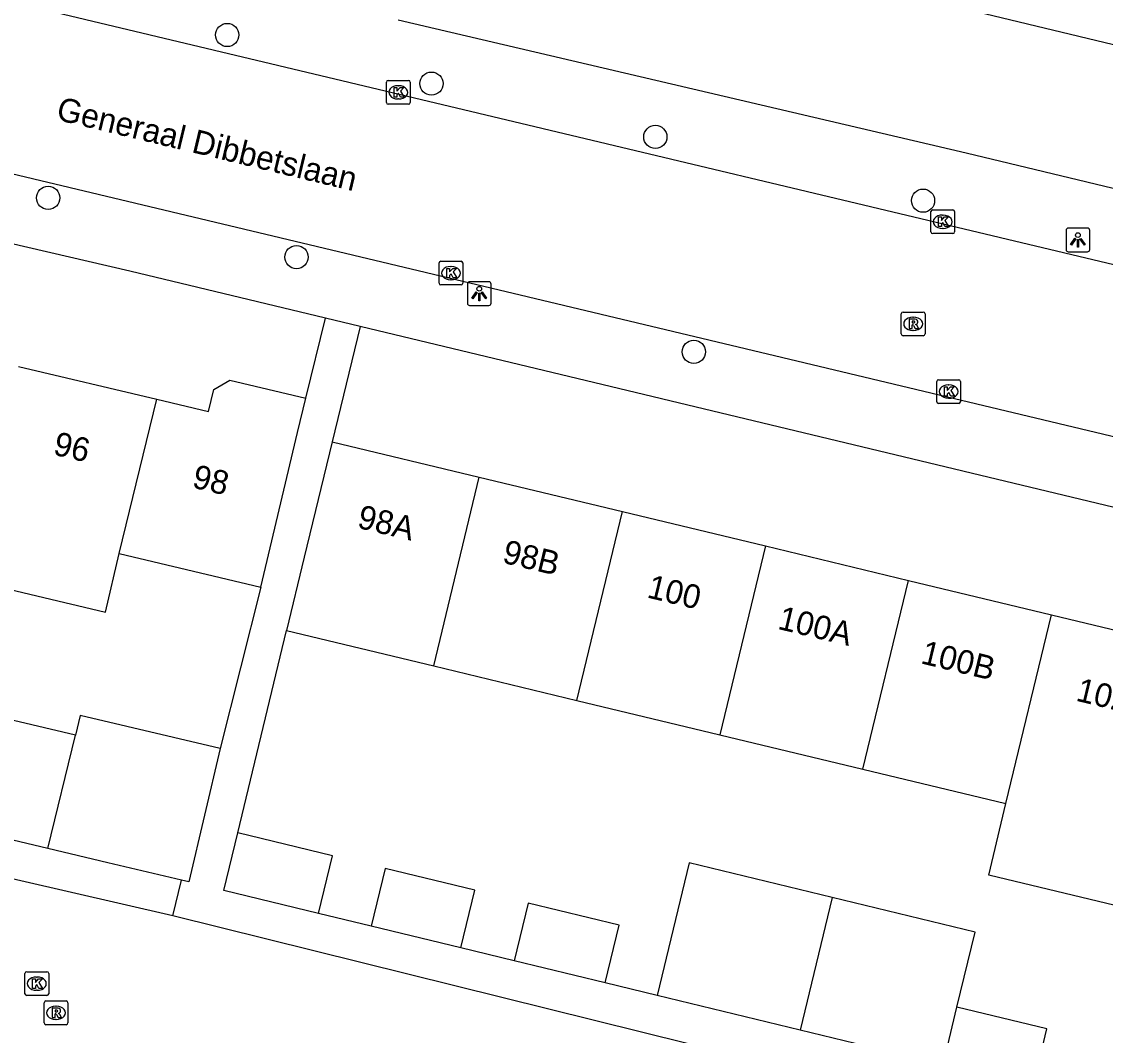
# Model space of a CAD drawing. Extents: x 161084 to 161928, y 385355 to 386522.
# Drawn here: x 161373.77 to 161419.44, y 385813.15 to 385855.89 of the extents above; entities that cross this region are included whole.
import ezdxf

# ---------------------------------------------------------------- set-up
doc = ezdxf.new("R2010")
doc.units = 0
for name, color, linetype in [('IMGEO_Boom', 7, 'Continuous'), ('IMGEO_Kolk', 7, 'Continuous'), ('IMGEO_Lichtpunt', 7, 'Continuous'), ('IMGEO_Openbare_ruimte_label', 7, 'Continuous'), ('IMGEO_Pand', 7, 'Continuous'), ('IMGEO_Pand_nummerreeks', 7, 'Continuous'), ('IMGEO_Rijbaan_lokaal_open', 7, 'Continuous'), ('IMGEO_Rioolput', 7, 'Continuous'), ('IMGEO_Voetpad_open', 7, 'Continuous')]:
    doc.layers.add(name, color=color, linetype=linetype)

msp = doc.modelspace()

# ---------------------------------------------------------------- linework, layer by layer
at = {"layer": 'IMGEO_Boom'}
for centre in [(161382.429, 385855.324), (161391.039, 385853.273), (161400.475, 385851.026), (161374.883, 385848.457), (161411.759, 385848.339), (161385.35, 385845.96), (161402.097, 385841.965)]:
    msp.add_circle(centre, 0.489, dxfattribs=at)
at = {"layer": 'IMGEO_Kolk'}
for p, q in [((161389.141, 385852.48), (161389.141, 385853.332)), ((161389.216, 385853.406), (161390.068, 385853.406)), ((161389.629, 385853.186), (161389.654, 385853.186)), ((161390.142, 385853.332), (161390.142, 385852.48)), ((161390.068, 385852.406), (161389.216, 385852.406)), ((161389.652, 385852.626), (161389.627, 385852.626)), ((161412.089, 385847.024), (161412.089, 385847.876)), ((161412.164, 385847.95), (161413.016, 385847.95)), ((161412.577, 385847.73), (161412.602, 385847.73)), ((161413.09, 385847.876), (161413.09, 385847.024)), ((161413.016, 385846.95), (161412.164, 385846.95)), ((161412.6, 385847.17), (161412.575, 385847.17)), ((161391.36, 385844.859), (161391.36, 385845.711)), ((161391.435, 385845.785), (161392.287, 385845.785)), ((161391.848, 385845.565), (161391.873, 385845.565)), ((161392.361, 385845.711), (161392.361, 385844.859)), ((161391.871, 385845.005), (161391.846, 385845.005)), ((161392.287, 385844.785), (161391.435, 385844.785)), ((161412.411, 385840.789), (161413.263, 385840.789)), ((161412.336, 385839.863), (161412.336, 385840.715)), ((161412.824, 385840.569), (161412.849, 385840.569)), ((161413.337, 385840.715), (161413.337, 385839.863)), ((161412.847, 385840.009), (161412.822, 385840.009)), ((161413.263, 385839.789), (161412.411, 385839.789)), ((161373.904, 385814.901), (161373.904, 385815.753)), ((161373.979, 385815.827), (161374.831, 385815.827)), ((161374.905, 385815.753), (161374.905, 385814.901)), ((161374.392, 385815.607), (161374.417, 385815.607)), ((161374.831, 385814.827), (161373.979, 385814.827)), ((161374.415, 385815.047), (161374.39, 385815.047))]:
    msp.add_line(p, q, dxfattribs=at)
for points in [[(161389.141, 385852.48), (161389.141, 385853.332)], [(161389.216, 385853.406), (161390.068, 385853.406)], [(161390.142, 385853.332), (161390.142, 385852.48)], [(161389.462, 385853.106), (161389.585, 385853.106), (161389.585, 385852.955), (161389.715, 385853.106), (161389.879, 385853.106), (161389.733, 385852.955), (161389.886, 385852.706), (161389.734, 385852.706), (161389.649, 385852.87), (161389.585, 385852.803), (161389.585, 385852.706), (161389.462, 385852.706), (161389.462, 385853.106)], [(161390.068, 385852.406), (161389.216, 385852.406)], [(161412.089, 385847.024), (161412.089, 385847.876)], [(161412.164, 385847.95), (161413.016, 385847.95)], [(161412.41, 385847.65), (161412.533, 385847.65), (161412.533, 385847.499), (161412.663, 385847.65), (161412.827, 385847.65), (161412.681, 385847.499), (161412.834, 385847.25), (161412.682, 385847.25), (161412.597, 385847.414), (161412.533, 385847.347), (161412.533, 385847.25), (161412.41, 385847.25), (161412.41, 385847.65)], [(161413.09, 385847.876), (161413.09, 385847.024)], [(161413.016, 385846.95), (161412.164, 385846.95)], [(161391.36, 385844.859), (161391.36, 385845.711)], [(161391.435, 385845.785), (161392.287, 385845.785)], [(161391.681, 385845.485), (161391.804, 385845.485), (161391.804, 385845.334), (161391.934, 385845.485), (161392.098, 385845.485), (161391.952, 385845.334), (161392.105, 385845.085), (161391.953, 385845.085), (161391.868, 385845.249), (161391.804, 385845.182), (161391.804, 385845.085), (161391.681, 385845.085), (161391.681, 385845.485)], [(161392.361, 385845.711), (161392.361, 385844.859)], [(161392.287, 385844.785), (161391.435, 385844.785)], [(161412.411, 385840.789), (161413.263, 385840.789)], [(161412.336, 385839.863), (161412.336, 385840.715)], [(161412.657, 385840.489), (161412.78, 385840.489), (161412.78, 385840.338), (161412.91, 385840.489), (161413.074, 385840.489), (161412.928, 385840.338), (161413.081, 385840.089), (161412.929, 385840.089), (161412.844, 385840.253), (161412.78, 385840.186), (161412.78, 385840.089), (161412.657, 385840.089), (161412.657, 385840.489)], [(161413.337, 385840.715), (161413.337, 385839.863)], [(161413.263, 385839.789), (161412.411, 385839.789)], [(161373.904, 385814.901), (161373.904, 385815.753)], [(161373.979, 385815.827), (161374.831, 385815.827)], [(161374.905, 385815.753), (161374.905, 385814.901)], [(161374.225, 385815.527), (161374.348, 385815.527), (161374.348, 385815.376), (161374.478, 385815.527), (161374.642, 385815.527), (161374.496, 385815.376), (161374.649, 385815.127), (161374.497, 385815.127), (161374.412, 385815.291), (161374.348, 385815.224), (161374.348, 385815.127), (161374.225, 385815.127), (161374.225, 385815.527)], [(161374.831, 385814.827), (161373.979, 385814.827)]]:
    msp.add_lwpolyline(points, dxfattribs=at)
for centre, start, end in [((161389.218, 385853.33), 91.552, 178.448), ((161389.218, 385853.33), 91.552, 178.448), ((161390.066, 385853.33), 1.552, 88.448), ((161390.066, 385853.33), 1.552, 88.448), ((161389.218, 385852.482), 181.552, 268.448), ((161389.218, 385852.482), 181.552, 268.448), ((161390.066, 385852.482), 271.552, 358.448), ((161390.066, 385852.482), 271.552, 358.448), ((161412.166, 385847.874), 91.552, 178.448), ((161412.166, 385847.874), 91.552, 178.448), ((161413.014, 385847.874), 1.552, 88.448), ((161413.014, 385847.874), 1.552, 88.448), ((161412.166, 385847.026), 181.552, 268.448), ((161412.166, 385847.026), 181.552, 268.448), ((161413.014, 385847.026), 271.552, 358.448), ((161413.014, 385847.026), 271.552, 358.448), ((161391.437, 385845.709), 91.552, 178.448), ((161391.437, 385845.709), 91.552, 178.448), ((161392.285, 385845.709), 1.552, 88.448), ((161392.285, 385845.709), 1.552, 88.448), ((161391.437, 385844.861), 181.552, 268.448), ((161391.437, 385844.861), 181.552, 268.448), ((161392.285, 385844.861), 271.552, 358.448), ((161392.285, 385844.861), 271.552, 358.448), ((161412.413, 385840.713), 91.552, 178.448), ((161412.413, 385840.713), 91.552, 178.448), ((161413.261, 385840.713), 1.552, 88.448), ((161413.261, 385840.713), 1.552, 88.448), ((161412.413, 385839.865), 181.552, 268.448), ((161412.413, 385839.865), 181.552, 268.448), ((161413.261, 385839.865), 271.552, 358.448), ((161413.261, 385839.865), 271.552, 358.448), ((161373.981, 385815.751), 91.552, 178.448), ((161373.981, 385815.751), 91.552, 178.448), ((161374.829, 385815.751), 1.552, 88.448), ((161374.829, 385815.751), 1.552, 88.448), ((161373.981, 385814.903), 181.552, 268.448), ((161373.981, 385814.903), 181.552, 268.448), ((161374.829, 385814.903), 271.552, 358.448), ((161374.829, 385814.903), 271.552, 358.448)]:
    msp.add_arc(centre, 0.0765, start, end, dxfattribs=at)
for centre, major_axis, ratio, start_param, end_param in [((161389.628, 385852.906), (-0.387, 0.002), 0.722429, 4.712389, 7.853982), ((161389.653, 385852.906), (-0.39, 0.002), 0.717154, 1.570796, 4.712389), ((161412.576, 385847.45), (-0.387, 0.002), 0.722429, 4.712389, 7.853982), ((161412.601, 385847.45), (-0.39, 0.002), 0.717154, 1.570796, 4.712389), ((161391.847, 385845.285), (-0.387, 0.002), 0.722429, 4.712389, 7.853982), ((161391.872, 385845.285), (-0.39, 0.002), 0.717154, 1.570796, 4.712389), ((161412.823, 385840.289), (-0.387, 0.002), 0.722429, 4.712389, 7.853982), ((161412.848, 385840.289), (-0.39, 0.002), 0.717154, 1.570796, 4.712389), ((161374.391, 385815.327), (-0.387, 0.002), 0.722429, 4.712389, 7.853982), ((161374.416, 385815.327), (-0.39, 0.002), 0.717154, 1.570796, 4.712389)]:
    msp.add_ellipse(centre, major_axis=major_axis, ratio=ratio, start_param=start_param, end_param=end_param, dxfattribs=at)
at = {"layer": 'IMGEO_Lichtpunt'}
for p, q in [((161418.688, 385847.182), (161417.88, 385847.182)), ((161418.688, 385847.182), (161417.88, 385847.182)), ((161417.786, 385847.087), (161417.786, 385846.28)), ((161417.786, 385847.087), (161417.786, 385846.28)), ((161418.782, 385846.28), (161418.782, 385847.087)), ((161418.782, 385846.28), (161418.782, 385847.087)), ((161417.88, 385846.186), (161418.688, 385846.186)), ((161417.88, 385846.186), (161418.688, 385846.186)), ((161393.456, 385844.92), (161392.648, 385844.92)), ((161393.456, 385844.92), (161392.648, 385844.92)), ((161392.554, 385844.825), (161392.554, 385844.018)), ((161392.554, 385844.825), (161392.554, 385844.018)), ((161393.55, 385844.018), (161393.55, 385844.825)), ((161393.55, 385844.018), (161393.55, 385844.825)), ((161392.648, 385843.924), (161393.456, 385843.924)), ((161392.648, 385843.924), (161393.456, 385843.924))]:
    msp.add_line(p, q, dxfattribs=at)
for points in [[(161418.16, 385846.751), (161418.199, 385846.723), (161418.011, 385846.461), (161417.973, 385846.488), (161418.16, 385846.751)], [(161418.372, 385846.723), (161418.41, 385846.75), (161418.597, 385846.488), (161418.558, 385846.46), (161418.372, 385846.723)], [(161418.262, 385846.703), (161418.309, 385846.703), (161418.309, 385846.381), (161418.262, 385846.381), (161418.262, 385846.703)], [(161392.928, 385844.489), (161392.967, 385844.461), (161392.779, 385844.199), (161392.741, 385844.226), (161392.928, 385844.489)], [(161393.03, 385844.441), (161393.077, 385844.441), (161393.077, 385844.119), (161393.03, 385844.119), (161393.03, 385844.441)], [(161393.14, 385844.461), (161393.178, 385844.488), (161393.365, 385844.226), (161393.326, 385844.198), (161393.14, 385844.461)]]:
    msp.add_lwpolyline(points, dxfattribs=at)
for centre in [(161418.285, 385846.885), (161393.053, 385844.623)]:
    msp.add_circle(centre, 0.0994, dxfattribs=at)
for centre, start, end in [((161417.88, 385847.087), 90, 180), ((161417.88, 385847.087), 90, 180), ((161418.688, 385847.087), 0, 90), ((161418.688, 385847.087), 0, 90), ((161417.88, 385846.28), 180, 270), ((161417.88, 385846.28), 180, 270), ((161418.688, 385846.28), 270, 0), ((161418.688, 385846.28), 270, 360), ((161392.648, 385844.825), 90, 180), ((161392.648, 385844.825), 90, 180), ((161393.456, 385844.825), 0, 90), ((161393.456, 385844.825), 0, 90), ((161392.648, 385844.018), 180, 270), ((161392.648, 385844.018), 180, 270), ((161393.456, 385844.018), 270, 0), ((161393.456, 385844.018), 270, 360)]:
    msp.add_arc(centre, 0.0946, start, end, dxfattribs=at)
at = {"layer": 'IMGEO_Pand'}
for points in [[(161420.137, 385854.826), (161414.342, 385856.219)], [(161373.629, 385841.35), (161379.457, 385839.969)], [(161379.457, 385839.969), (161381.647, 385839.45), (161381.866, 385840.374), (161382.535, 385840.771), (161385.737, 385840.012)], [(161377.882, 385833.457), (161379.457, 385839.969)], [(161383.848, 385832.043), (161384.24, 385833.697), (161385.393, 385838.562), (161385.737, 385840.012)], [(161386.849, 385838.175), (161385.679, 385833.314), (161384.932, 385830.212)], [(161386.849, 385838.175), (161393.056, 385836.681)], [(161391.14, 385828.72), (161393.056, 385836.681)], [(161393.056, 385836.681), (161399.084, 385835.23)], [(161397.168, 385827.27), (161399.084, 385835.23)], [(161399.084, 385835.23), (161405.111, 385833.78)], [(161372.084, 385834.831), (161371.5, 385832.368), (161377.298, 385830.994), (161377.882, 385833.457)], [(161405.111, 385833.78), (161403.196, 385825.821)], [(161405.111, 385833.78), (161411.139, 385832.329)], [(161377.882, 385833.457), (161383.848, 385832.043)], [(161409.225, 385824.372), (161411.139, 385832.329)], [(161411.139, 385832.329), (161417.167, 385830.878)], [(161415.253, 385822.922), (161417.167, 385830.878)], [(161417.167, 385830.878), (161423.195, 385829.427)], [(161384.932, 385830.212), (161391.14, 385828.72)], [(161391.14, 385828.72), (161397.168, 385827.27)], [(161376.031, 385825.802), (161370.268, 385827.173)], [(161397.168, 385827.27), (161403.196, 385825.821)], [(161382.138, 385825.241), (161376.233, 385826.638), (161376.031, 385825.802)], [(161374.876, 385821.027), (161376.031, 385825.802)], [(161403.196, 385825.821), (161409.225, 385824.372)], [(161382.138, 385825.241), (161380.808, 385819.616), (161380.498, 385819.69)], [(161409.225, 385824.372), (161415.253, 385822.922)], [(161421.281, 385821.473), (161420.556, 385818.457), (161414.528, 385819.906), (161415.253, 385822.922)], [(161374.876, 385821.027), (161369.136, 385822.392)], [(161386.272, 385818.291), (161382.294, 385819.256), (161382.883, 385821.686)], [(161386.272, 385818.291), (161386.861, 385820.721), (161382.883, 385821.686)], [(161380.498, 385819.69), (161377.399, 385820.427), (161374.876, 385821.027)], [(161407.923, 385818.958), (161401.897, 385820.419), (161400.551, 385814.828)], [(161392.281, 385816.834), (161392.87, 385819.264), (161389.085, 385820.182), (161388.5, 385817.751)], [(161407.923, 385818.958), (161406.578, 385813.367)], [(161413.188, 385814.337), (161413.949, 385817.497), (161407.923, 385818.958)], [(161398.355, 385815.361), (161398.944, 385817.791), (161395.11, 385818.721), (161394.525, 385816.29)], [(161392.281, 385816.834), (161388.5, 385817.751)], [(161398.355, 385815.361), (161394.525, 385816.29)], [(161406.578, 385813.367), (161400.551, 385814.828)], [(161412.603, 385811.906), (161413.188, 385814.337)], [(161416.393, 385810.987), (161416.978, 385813.418), (161413.188, 385814.337)], [(161412.603, 385811.906), (161406.578, 385813.367)]]:
    msp.add_lwpolyline(points, dxfattribs=at)
at = {"layer": 'IMGEO_Rijbaan_lokaal_open'}
for points in [[(161469.483, 385833.788), (161447.797, 385838.953), (161443.995, 385839.867), (161441.191, 385840.536), (161366.79, 385858.283), (161357.51, 385860.468), (161341.03, 385864.349), (161340.797, 385864.409), (161340.28, 385864.577), (161339.781, 385864.791), (161339.302, 385865.048), (161338.849, 385865.348), (161338.424, 385865.686), (161338.031, 385866.061), (161337.673, 385866.47), (161337.353, 385866.909), (161337.074, 385867.375), (161336.837, 385867.864), (161336.645, 385868.372)], [(161351.902, 385854.625), (161361.37, 385852.342), (161406.44, 385841.585), (161439.496, 385833.681), (161487.09, 385822.28), (161490.645, 385821.437), (161540.178, 385809.69), (161553.334, 385806.533), (161560.913, 385804.952), (161564.397, 385804.459), (161572.843, 385803.627), (161581.329, 385803.552), (161583.838, 385803.676), (161586.385, 385803.89), (161616.338, 385805.286)], [(161380.136, 385818.183), (161343.813, 385826.554)], [(161411.784, 385810.335), (161380.136, 385818.183)]]:
    msp.add_lwpolyline(points, dxfattribs=at)
at = {"layer": 'IMGEO_Rioolput'}
for p, q in [((161410.842, 385842.718), (161410.842, 385843.57)), ((161410.917, 385843.644), (161411.769, 385843.644)), ((161411.843, 385843.57), (161411.843, 385842.718)), ((161411.33, 385843.424), (161411.355, 385843.424)), ((161411.769, 385842.644), (161410.917, 385842.644)), ((161411.353, 385842.864), (161411.328, 385842.864)), ((161374.713, 385813.67), (161374.713, 385814.522)), ((161374.788, 385814.596), (161375.64, 385814.596)), ((161375.201, 385814.376), (161375.226, 385814.376)), ((161375.714, 385814.522), (161375.714, 385813.67)), ((161375.64, 385813.596), (161374.788, 385813.596)), ((161375.224, 385813.816), (161375.199, 385813.816))]:
    msp.add_line(p, q, dxfattribs=at)
for points in [[(161410.842, 385842.718), (161410.842, 385843.57)], [(161410.917, 385843.644), (161411.769, 385843.644)], [(161411.843, 385843.57), (161411.843, 385842.718)], [(161411.431, 385843.342), (161411.179, 385843.344), (161411.179, 385842.944)], [(161411.179, 385842.944), (161411.303, 385842.944), (161411.303, 385843.106), (161411.314, 385843.106)], [(161411.357, 385843.263), (161411.303, 385843.263), (161411.303, 385843.182)], [(161411.303, 385843.182), (161411.355, 385843.182)], [(161411.361, 385843.077), (161411.432, 385842.944), (161411.572, 385842.944), (161411.507, 385843.07)], [(161411.769, 385842.644), (161410.917, 385842.644)], [(161374.713, 385813.67), (161374.713, 385814.522)], [(161374.788, 385814.596), (161375.64, 385814.596)], [(161375.302, 385814.294), (161375.05, 385814.296), (161375.05, 385813.896)], [(161375.714, 385814.522), (161375.714, 385813.67)], [(161375.05, 385813.896), (161375.174, 385813.896), (161375.174, 385814.058), (161375.185, 385814.058)], [(161375.228, 385814.215), (161375.174, 385814.215), (161375.174, 385814.134)], [(161375.174, 385814.134), (161375.226, 385814.134)], [(161375.232, 385814.029), (161375.303, 385813.896), (161375.443, 385813.896), (161375.378, 385814.022)], [(161375.64, 385813.596), (161374.788, 385813.596)]]:
    msp.add_lwpolyline(points, dxfattribs=at)
for centre, radius, start, end in [((161410.919, 385843.568), 0.0765, 91.552, 178.448), ((161410.919, 385843.568), 0.0765, 91.552, 178.448), ((161411.767, 385843.568), 0.0765, 1.552, 88.448), ((161411.767, 385843.568), 0.0765, 1.552, 88.448), ((161411.313, 385843.053), 0.0533, 26.0293, 88.6989), ((161411.339, 385843.371), 0.19, 274.7715, 282.9687), ((161411.363, 385843.167), 0.0964, 77.0061, 93.1865), ((161411.377, 385843.224), 0.0378, 276.6634, 79.6772), ((161411.43, 385843.232), 0.109, 350.3612, 89.416), ((161411.428, 385843.232), 0.112, 277.5842, 350.9817), ((161411.412, 385843.017), 0.108, 29.5134, 73.7905), ((161410.919, 385842.72), 0.0765, 181.552, 268.448), ((161410.919, 385842.72), 0.0765, 181.552, 268.448), ((161411.767, 385842.72), 0.0765, 271.552, 358.448), ((161411.767, 385842.72), 0.0765, 271.552, 358.448), ((161374.79, 385814.52), 0.0765, 91.552, 178.448), ((161374.79, 385814.52), 0.0765, 91.552, 178.448), ((161375.301, 385814.184), 0.109, 350.3612, 89.416), ((161375.638, 385814.52), 0.0765, 1.552, 88.448), ((161375.638, 385814.52), 0.0765, 1.552, 88.448), ((161375.184, 385814.005), 0.0533, 26.0293, 88.6989), ((161375.21, 385814.323), 0.19, 274.7715, 282.9687), ((161375.234, 385814.119), 0.0964, 77.0061, 93.1865), ((161375.248, 385814.176), 0.0378, 276.6634, 79.6772), ((161375.299, 385814.184), 0.112, 277.5842, 350.9817), ((161375.283, 385813.969), 0.108, 29.5134, 73.7905), ((161374.79, 385813.672), 0.0765, 181.552, 268.448), ((161374.79, 385813.672), 0.0765, 181.552, 268.448), ((161375.638, 385813.672), 0.0765, 271.552, 358.448), ((161375.638, 385813.672), 0.0765, 271.552, 358.448)]:
    msp.add_arc(centre, radius, start, end, dxfattribs=at)
for centre, major_axis, ratio, start_param, end_param in [((161411.329, 385843.144), (-0.387, 0.002), 0.722429, 4.712389, 7.853982), ((161411.354, 385843.144), (-0.39, 0.002), 0.717154, 1.570796, 4.712389), ((161375.2, 385814.096), (-0.387, 0.002), 0.722429, 4.712389, 7.853982), ((161375.225, 385814.096), (-0.39, 0.002), 0.717154, 1.570796, 4.712389)]:
    msp.add_ellipse(centre, major_axis=major_axis, ratio=ratio, start_param=start_param, end_param=end_param, dxfattribs=at)
at = {"layer": 'IMGEO_Voetpad_open'}
for points in [[(161389.632, 385855.958), (161413.574, 385850.358), (161441.922, 385843.544), (161448.132, 385842.052)], [(161386.576, 385843.385), (161378.321, 385845.368), (161353.49, 385851.125)], [(161385.737, 385840.012), (161386.576, 385843.385)], [(161388.04, 385843.033), (161386.576, 385843.385)], [(161388.04, 385843.033), (161386.849, 385838.175)], [(161466.809, 385824.108), (161438.833, 385830.83), (161388.04, 385843.033)], [(161383.848, 385832.043), (161382.138, 385825.241)], [(161382.883, 385821.686), (161384.932, 385830.212)], [(161380.136, 385818.183), (161380.498, 385819.69)], [(161388.5, 385817.751), (161386.272, 385818.291)], [(161394.525, 385816.29), (161392.281, 385816.834)], [(161400.551, 385814.828), (161398.355, 385815.361)]]:
    msp.add_lwpolyline(points, dxfattribs=at)

# ---------------------------------------------------------------- texts
at = {"layer": 'IMGEO_Openbare_ruimte_label'}
msp.add_text('Generaal Dibbetslaan', height=1, rotation=346.4641, dxfattribs=at).set_placement((161375.18, 385851.761))
at = {"layer": 'IMGEO_Pand_nummerreeks'}
for s, rotation, p in [('96', 346.6667, (161375.052, 385837.642)), ('98', 346.6667, (161380.909, 385836.254)), ('98A', 346.467, (161387.867, 385834.557)), ('98B', 346.467, (161393.984, 385833.084)), ('100', 346.467, (161400.083, 385831.616)), ('100A', 346.467, (161405.591, 385830.291)), ('100B', 346.4597, (161411.618, 385828.839)), ('102', 346.4725, (161418.161, 385827.264))]:
    msp.add_text(s, height=1, rotation=rotation, dxfattribs=at).set_placement(p)

doc.saveas('drawing.dxf')
